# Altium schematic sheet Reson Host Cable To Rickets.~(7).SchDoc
size Tabloid; Organization: Monterey Bay Aquarium Research Institute; Address1: 7700 Sandholdt Rd; Address2: Moss Landing, CA 95039-9644; CompanyName: MBARI; PageSetup: Record=PageOptions|CenterHorizontal=True|CenterVertical=True|PrintScale=0.96|XCorrection=1.00|YCorrection=1.00|PrintKind=0|BorderSize=5000000|LeftOffset=0|BottomOffset=0|Orientation=2|PaperLength=1000|PaperWidth=1000|Scale=100|PaperSource=7|PrintQuality=-4|MediaType=1|DitherType=10|PaperKind=11x17|PrintScaleMode=1
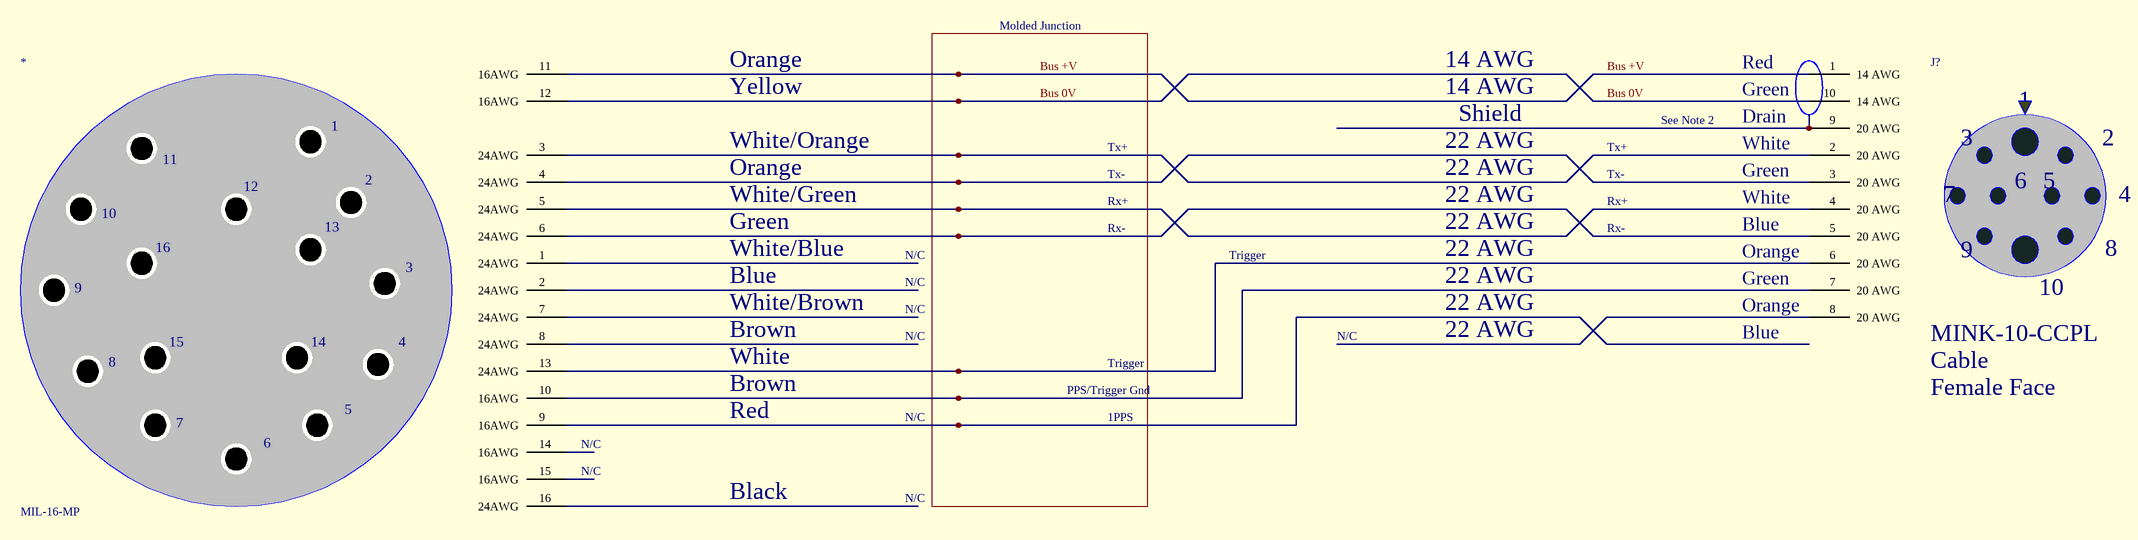
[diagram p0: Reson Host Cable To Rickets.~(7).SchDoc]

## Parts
*  MIL-16-MP
J?  MINK-10-CCPL  DescSheet: Cable  View: Female Face

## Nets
Bus 0V: *.12(16AWG) J?.10(14_AWG)
Bus +V: *.11(16AWG) J?.1(14_AWG)
Net*_3: *.3(24AWG) J?.2(20_AWG)
Net*_4: *.4(24AWG) J?.3(20_AWG)
Net*_5: *.5(24AWG) J?.4(20_AWG)
Net*_6: *.6(24AWG) J?.5(20_AWG)
Net*_10: *.10(16AWG) J?.7(20_AWG)
Net*_13: *.13(24AWG) J?.6(20_AWG)

Not connected (* = marked no-connect by the designer): * 1(24AWG) 2(24AWG) 7(24AWG) 8(24AWG) 9(16AWG) 14(16AWG) 15(16AWG) 16(24AWG); J? 8(20_AWG) 9(20_AWG)

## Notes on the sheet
- Molded Junction
- Orange
- Yellow
- 14 AWG
- Shield
- See Note 2
- Red
- Green
- Drain
- White/Orange
- Tx+
- Tx-
- 22 AWG
- White
- White/Blue
- White/Green
- N/C
- Rx+
- Rx-
- Trigger
- Blue
- (near J?) Orange
- White/Brown
- Brown
- PPS/Trigger Gnd
- 1PPS
- Black

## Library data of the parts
J? = SEACON-MINK-10-CCP-SOC: Seacon MINK-10/L-CCP Connector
